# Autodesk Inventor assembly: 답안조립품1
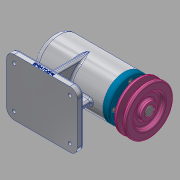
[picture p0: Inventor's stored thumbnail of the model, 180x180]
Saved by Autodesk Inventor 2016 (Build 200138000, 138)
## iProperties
Created: 2020-10
Part Number: 답안조립품1
Document SubType Name: Assembly
Designer: user
Author: user
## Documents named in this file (12)
- C:\Users\user\Desktop\701004V1004\답안조립품1.iam
- C:\Users\user\Desktop\701004V1004\1.본체.ipt
- C:\Users\user\Desktop\701004V1004\베어링 51202.ipt
- C:\Users\user\Desktop\701004V1004\어댑터슬리브.ipt
- C:\Users\user\Desktop\701004V1004\베어링 6004.ipt
- C:\Users\user\Desktop\701004V1004\축.ipt
- C:\Users\user\Desktop\701004V1004\커버.ipt
- C:\Users\user\Desktop\701004V1004\볼트 M4.ipt
- C:\Users\user\Desktop\701004V1004\Ű 5 x 5 x 16.ipt
- C:\Users\user\Desktop\701004V1004\오일 실.ipt
- C:\Users\user\Desktop\701004V1004\V벨트풀리.ipt
- C:\Users\user\Desktop\701004V1004\멈춤나사 M3.ipt
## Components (3 placed, 3 different names)
1. 1.본체:1
2. Ű 5 x 5 x 16:1
3. V벨트풀리:1 — 플러쉬:1
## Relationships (1: Flush 1)
- 플러쉬:1 [Flush]: V벨트풀리:1
